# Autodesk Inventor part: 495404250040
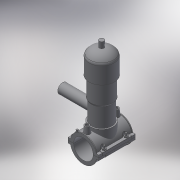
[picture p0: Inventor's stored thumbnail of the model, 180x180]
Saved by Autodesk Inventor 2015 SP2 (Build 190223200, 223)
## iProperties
Created: 2017-07
Part Number: 495404250040
Material: Generic
Description: PLASSON TAPPING VALVE 250-40
Document SubType Name: Modeling
Designer: KIM
Density: 1 g/cm^3
Appearance: Default
Author: KIM
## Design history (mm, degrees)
derived "495404-4954S4.ipt"
feature "Solid1::495404-4954S4.ipt"
feature "Solid2::495404-4954S4.ipt"
tag "TaggingFeature1"
body "Solid1"
body "Solid2"
other parameters: "d2" = 327.6, "d3" = 62.5, "d4" = 176, "d5" = 0, "d6" = 0.1, "d8" = 0, "d19" = 6, "d20" = 6, "d21" = 105.6, "d23" = 0, "d24" = 52.8, "d26" = 0, "d27" = 3, "d28" = 3, "d29" = 3, "d30" = 83.33333, "d31" = 6, "d32" = 0, "d33" = 0, "d34" = 0.6, "d40" = 152.1, "d47" = 192.25, "d70" = 15, "d72" = 0, "d73" = 6, "d75" = 5, "d76" = 0, "d77" = 12.5, "d78" = 155, "d79" = 15, "d80" = 70.4, "d82" = 5 deg, "d84" = 4, "d85" = 14, "d86" = 0, "d87" = 3, "d88" = 0, "d89" = 1, "d90" = 1, "d91" = 140.8, "d92" = 0, "d93" = 0.5, "d94" = 131.57895, "d96" = 301.275, "d97" = 3.52, "d98" = 0, "d120" = 140 deg, "d121" = 24.228, "d122" = 20 deg, "d123" = 585, "d124" = 175.5, "d126" = 0, "d143" = 257.5, "d145" = 32.69231, "d149" = 3.75, "d150" = 35.96154, "d153" = 176, "d154" = 0, "d156" = 146.25, "d157" = 160 deg, "d159" = 8.5, "d161" = 3.75, "d162" = 105.6, "d163" = 0, "d164" = 125, "d167" = 25, "d168" = 142.68293, "d170" = 3.75, "d172" = 0, "d173" = 1, "d175" = 125, "d176" = 20 deg, "d177" = 17.5, "d178" = 42.5, "d180" = 0, "d183" = 17, "d184" = 14, "d185" = 57.2, "d186" = 57.2, "d187" = 146.25, "d188" = 12.75, "d189" = 17.5, "d190" = 0, "d191" = 219.375, "d193" = 8.5, "d194" = 4.4, "d195" = 90 deg, "d197" = 0, "d199" = 0, "d205" = 14.64, "d206" = 81.33333, "d207" = 244, "d208" = 224.48, "d209" = 207.4, "d210" = 200.08, "d211" = 146.4, "d212" = 85.4, "d213" = 65.88, "d214" = 73.2, "d216" = 21.96, "d217" = 70.76, "d218" = 80.52, "d222" = 0, "d223" = 292.5, "d224" = 137, "d225" = 46, "d229" = 137, "d230" = 0, "B_" = 252, "H_" = 137, "L_" = 176, "d_t" = 6, "H_1" = 46, "H_2" = 244, "d148" = 3.75, "d160" = 3.75, "d169" = 3.75, "d192" = 8.5, "d228" = 32
